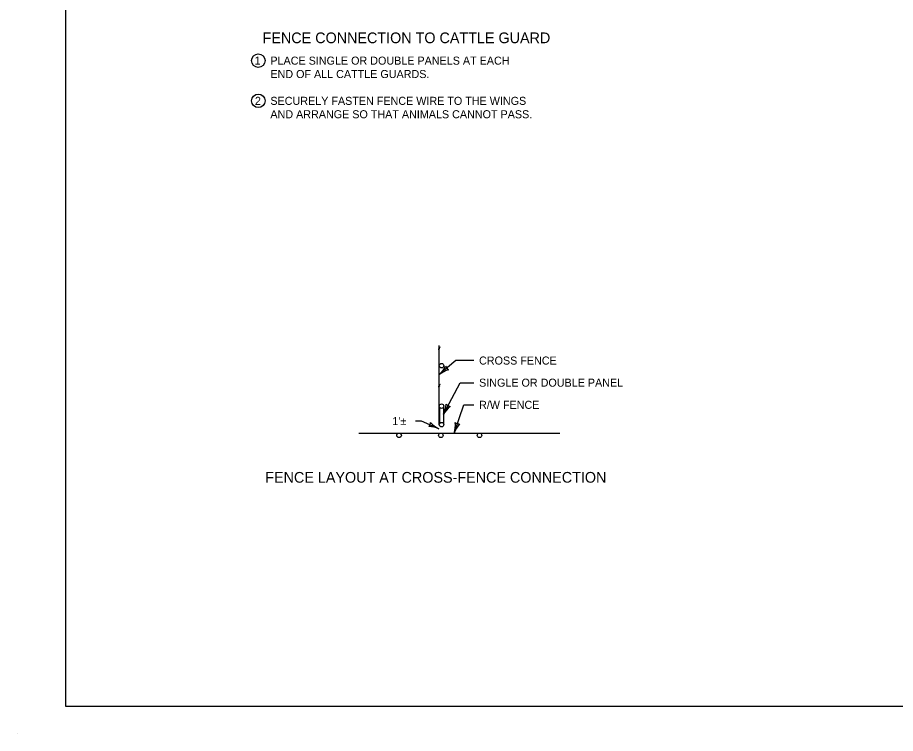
# Model space of a CAD drawing. Extents: x 49991.4 to 50021, y 49987.6 to 50011.4.
# Drawn here: x 49999.02 to 50005.57, y 49987.6 to 49992.94 of the extents above; entities that cross this region are included whole.
import ezdxf

# ---------------------------------------------------------------- set-up
doc = ezdxf.new("R2010")
doc.units = 0
for name, color, linetype in [('Level 1', 7, 'Continuous'), ('Level 2', 7, 'Continuous'), ('Level 3', 7, 'Continuous')]:
    doc.layers.add(name, color=color, linetype=linetype)

msp = doc.modelspace()

# ---------------------------------------------------------------- linework, layer by layer
at = {"layer": 'Level 1'}
for p, q in [((50002.1697, 49989.9017), (50002.1697, 49990.4929)), ((50002.1724, 49990.0317), (50002.1724, 49989.9113)), ((50002.2004, 49990.0311), (50002.2004, 49989.9107)), ((50001.5696, 49989.8396), (50003.0697, 49989.8396)), ((49999.0245, 49987.5988), (49999.0245, 49987.5988))]:
    msp.add_line(p, q, dxfattribs=at)
msp.add_lwpolyline([(49999.3835, 49998.9992), (50016.7501, 49998.9992), (50016.7501, 49987.7988), (49999.3835, 49987.7988)], close=True, dxfattribs=at)
for centre in [(50002.1865, 49990.3417), (50002.1866, 49990.0404), (50002.1865, 49989.9023), (50001.8697, 49989.8226), (50002.1814, 49989.8226), (50002.4696, 49989.8226)]:
    msp.add_circle(centre, 0.0169, dxfattribs=at)
for points in [[(50002.1611, 49990.4645), (50002.1724, 49990.4702), (50002.1668, 49990.4702), (50002.1724, 49990.4758), (50002.1668, 49990.4758), (50002.1781, 49990.4815)], [(50002.162, 49990.1859), (50002.1733, 49990.1915), (50002.1676, 49990.1915), (50002.1733, 49990.1972), (50002.1676, 49990.1972), (50002.1788, 49990.2029)]]:
    msp.add_spline(points, degree=3, dxfattribs=at)
at = {"layer": 'Level 2'}
for centre in [(50000.8199, 49992.6172), (50000.8199, 49992.3172)]:
    msp.add_circle(centre, 0.0501, dxfattribs=at)
at = {"layer": 'Level 3'}
for p, q in [((50002.2937, 49990.3801), (50002.1697, 49990.2754)), ((50002.4262, 49990.3801), (50002.2937, 49990.3801)), ((50002.2004, 49989.979), (50002.3242, 49990.2151)), ((50002.3242, 49990.2151), (50002.4262, 49990.2151)), ((50002.2805, 49989.8396), (50002.3519, 49990.05)), ((50002.3519, 49990.05), (50002.4262, 49990.05)), ((50002.0367, 49989.9284), (50001.9915, 49989.9284)), ((50002.1674, 49989.8714), (50002.0367, 49989.9284))]:
    msp.add_line(p, q, dxfattribs=at)
for centre, radius, start, end in [((50002.0108, 49990.4458), 0.233, 313.00355, 332.2534), ((50002.3061, 49990.0997), 0.2223, 107.63225, 127.81576), ((50002.2677, 49990.3581), 0.0548, 202.31506, 238.03742), ((50001.989, 49990.0769), 0.233, 335.15766, 354.40751), ((50002.3929, 49989.8677), 0.2223, 129.78636, 149.96987), ((50002.26, 49990.0925), 0.0548, 224.46917, 260.19153), ((50002.0505, 49989.924), 0.0548, 317.92356, 353.64592), ((50002.0825, 49989.6544), 0.233, 68.61205, 87.8619), ((50002.2669, 49990.0702), 0.2223, 223.24075, 243.42426), ((50002.0565, 49989.9035), 0.233, 344.08248, 3.33233), ((50002.4879, 49989.7595), 0.2223, 138.71118, 158.89469), ((50002.3217, 49989.961), 0.0548, 233.39399, 269.11635)]:
    msp.add_arc(centre, radius, start, end, dxfattribs=at)

# ---------------------------------------------------------------- texts
at = {"layer": 'Level 2'}
for s, height, p in [('FENCE CONNECTION TO CATTLE GUARD', 0.08, (50000.8519, 49992.7472)), ('1', 0.06, (50000.7926, 49992.5876)), ('PLACE SINGLE OR DOUBLE PANELS AT EACH', 0.06, (50000.91, 49992.5872)), ('END OF ALL CATTLE GUARDS.', 0.06, (50000.91, 49992.4872)), ('2', 0.06, (50000.7947, 49992.2872)), ('SECURELY FASTEN FENCE WIRE TO THE WINGS', 0.06, (50000.91, 49992.2872)), ('AND ARRANGE SO THAT ANIMALS CANNOT PASS.', 0.06, (50000.91, 49992.1872)), ('CROSS FENCE', 0.06, (50002.4662, 49990.3501)), ('SINGLE OR DOUBLE PANEL', 0.06, (50002.4662, 49990.1851)), ('R/W FENCE', 0.06, (50002.4662, 49990.02)), ("1'±", 0.06, (50001.8193, 49989.8984)), ('FENCE LAYOUT AT CROSS-FENCE CONNECTION', 0.08, (50000.8719, 49989.4691))]:
    msp.add_text(s, height=height, dxfattribs=at).set_placement(p)

doc.saveas('drawing.dxf')
